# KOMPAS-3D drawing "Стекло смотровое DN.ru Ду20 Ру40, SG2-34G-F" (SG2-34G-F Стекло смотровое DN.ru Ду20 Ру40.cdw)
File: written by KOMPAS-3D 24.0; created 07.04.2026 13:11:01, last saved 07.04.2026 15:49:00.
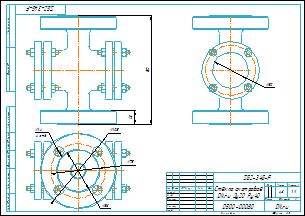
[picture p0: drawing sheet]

Document properties: Автор: Main; Форматы листов документа: A3; Полное имя файла: SG2-34G-F Стекло смотровое DN.ru Ду20 Ру40.m3d; Масса: 4.8; Наименование: Стекло смотровое DN.ru Ду20 Ру40; Количество листов документа: 1; Примечание: D500-00080

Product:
- Body: Тело 1  | qty 1
    Масса: 3.869459
- Part/product: Стекло смотровое DN.ru Ду20 Ру40  | designation SG2-34G-F
    Масса: 4.8
    Раздел спецификации: Прочие изделия
    Примечание: D500-00080

Views: Вид 1, Снизу, Проекционный вид 2
Referenced files in D:\DN.ru Аутсерс\Стекло смотровое DN.ru\Стекло смотровое DN.ru SG2-34G-F тип В ГОСТ 21836-2021 Ду100 Ру16, углеродистая сталь, фланцевое\: SG2-34G-F тип В Стекло смотровое DN.ru Ду100 Ру16.m3d, SG2-34G-F тип ВСтекло смотровое DN.ru Ду100 Ру16.cdw
Referenced files in D:\DN.ru Аутсерс\Стекло смотровое DN.ru\SG2-34G-F Стекло смотровое DN.ru Ду20 Ру40\: SG2-34G-F Стекло смотровое DN.ru Ду20 Ру40.m3d
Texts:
  SG2-34G-F
  Стекло смотровое
  DN.ru Ду20 Ру40
  Стекло смотровое DN.ru Ду20 Ру40
  SG2-34G-F Стекло смотровое DN.ru Ду20 Ру40
Dimensions and other numbers on the sheet: 0; 3; 2; 4; 150; 18; 14; 4 отв.; 105; 75; 58; 1:1; 1; 4,8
